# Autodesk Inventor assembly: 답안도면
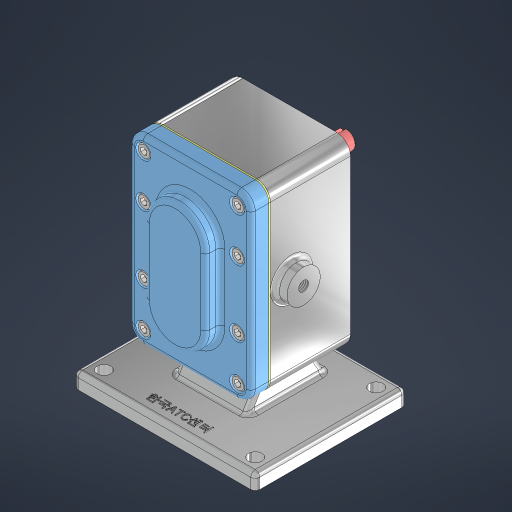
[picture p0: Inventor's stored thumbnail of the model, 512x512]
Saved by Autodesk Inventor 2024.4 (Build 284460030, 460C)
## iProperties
Created: 2026-10
Part Number: 답안도면
Document SubType Name: Assembly
Designer: user
Author: user
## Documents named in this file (11)
- C:\Users\user\Desktop\761003V1012\답안도면.iam
- C:\Users\user\Desktop\761003V1012\본체.ipt
- C:\Users\user\Desktop\761003V1012\베어링 부시\베어링 부시\베어링 부시.ipt
- C:\Users\user\Desktop\761003V1012\구동 축\구동 축\구동 축.ipt
- C:\Users\user\Desktop\761003V1012\종동 축\종동 축\종동 축.ipt
- C:\Users\user\Desktop\761003V1012\평행 키 6x6x18\평행 키 6x6x18\평행 키 6x6x18.ipt
- C:\Users\user\Desktop\761003V1012\스퍼 기어\스퍼 기어\스퍼 기어.ipt
- C:\Users\user\Desktop\761003V1012\개스킷\개스킷\개스킷.ipt
- C:\Users\user\Desktop\761003V1012\커버\커버\커버.ipt
- C:\Users\user\Desktop\761003V1012\6각 구멍붙이 볼트 M5x16\6각 구멍붙이 볼트 M5x16\6각 구멍붙이 볼트 M5x16.ipt
- C:\Users\user\Desktop\761003V1012\오일 실 16 28 7\오일 실 16 28 7\오일 실 16 28 7.ipt
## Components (10 placed, 3 different names)
1. 구동 축:1
2. 개스킷:1
3. 6각 구멍붙이 볼트 M5x16:1
4. 6각 구멍붙이 볼트 M5x16:2
5. 6각 구멍붙이 볼트 M5x16:3
6. 6각 구멍붙이 볼트 M5x16:4
7. 6각 구멍붙이 볼트 M5x16:5
8. 6각 구멍붙이 볼트 M5x16:6
9. 6각 구멍붙이 볼트 M5x16:7
10. 6각 구멍붙이 볼트 M5x16:8
